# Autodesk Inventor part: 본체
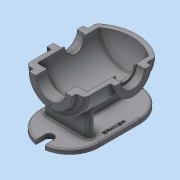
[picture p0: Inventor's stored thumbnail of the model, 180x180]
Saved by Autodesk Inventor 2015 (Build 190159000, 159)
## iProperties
Created: 2016-02
Part Number: 본체
Material: 알루미늄 6061
Document SubType Name: Modeling
Designer: mduedu
Density: 2.71 g/cm^3
Mass: 2164.68 g
Surface Area: 1516.74 cm^2
Volume: 798.775 cm^3
Appearance: 기본값
Author: mduedu
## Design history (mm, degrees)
sketch "스케치2"
  geometry: L1 (0, 90)-(0, -90); L2 (65, -65.993)-(65, 90); L3 (65, 90)-(0, 90); A1 r 100 centre (0, 10) between (0, -90) and (65, -65.993); 2 further points
  constraints: 6 end point, 2 point on circle, 1 centre point, 1 coincident, 1 horizontal, 1 midpoint, 1 parallel, 1 point on line, 1 vertical
  dimensions: "d3" = 180 distance of L1.start L1.end; "d5" = 130 diameter of L2 L1; "d6" = 100 radius of A1
revolve "회전1" sketch "스케치2" stored, may be unused: angle "d7" = 90 deg
sketch "스케치3"
  geometry: C1 r 47.5 at (0, 0); 1 further point
  constraints: 1 centre point, 1 coincident
  dimensions: "d8" = 95 diameter of C1
extrude "돌출2" join sketch "스케치3" distance "d10" = 10; taper "d11" = 0 deg
sketch "스케치5"
  geometry: L1 (47.5, 100)-(47.5, 90) reference; L2 (47.5, 90)-(65, 90) reference; L3 (65, 90)-(65, -65.993) reference; L4 (-65, -65.993)-(-65, 90) reference; L5 (-65, 90)-(-47.5, 90) reference; L6 (-47.5, 90)-(-47.5, 100) reference; L7 (-47.5, 100)-(47.5, 100) reference; L8 (55, 75)-(55, -61.239); L9 (0, 75)-(55, 75); L10 (0, 75)-(0, -80); A1 r 100 centre (0, 10) between (-65, -65.993) and (0, -90) reference; A2 r 100 centre (0, 10) between (0, -90) and (65, -65.993) reference; A3 r 90 centre (0, 10) between (0, -80) and (55, -61.239); 1 further point
  constraints: 6 end point, 2 point on circle, 1 centre point, 1 parallel, 1 perpendicular, 1 point on line, 1 vertical
  dimensions: "d13" = 10 distance between parallel lines of L3 L8; "d14" = 10 radial gap between concentric circles of A3 A1; "d15" = 15 distance between parallel lines of L9 L2
revolve "회전2" sketch "스케치5" stored, may be unused: angle "d16" = 90 deg
hole "구멍1" diameter "d19" = 65; stored, may be unused: countersink angle "d23" = 90 deg, drill point angle "d25" = 118 deg; dims "d17" = 10, "d18" = 10, "d20" = 6, "d21" = 4, "d22" = 2, "d24" = 8
node "작업 평면1"
sketch "스케치6"
  geometry: L1 (47.5, 100)-(-47.5, 100) reference; C1 r 40 at (0, -7); 1 further point
  constraints: 1 centre point, 1 vertical alignment
  dimensions: "d27" = 80 diameter of C1; "d29" = 107 distance from line of C1.centre L1
extrude "돌출3" join sketch "스케치6" stored distance "d30" = 10; taper "d31" = 0 deg
hole "구멍2" diameter "d34" = 42; stored, may be unused: countersink angle "d38" = 90 deg, drill point angle "d40" = 118 deg; dims "d32" = 10, "d33" = 10, "d35" = 6, "d36" = 52, "d37" = 18, "d39" = 8
sketch "스케치7" dims "d41" = 65
  geometry: C1 r 40 at (0, 0) reference; 3 further points
  constraints: 2 vertical alignment, 1 coincident, 2 other
hole "구멍3" sketch "스케치7" at (0, 32.5) diameter "d43" = 3.242; stored, may be unused: countersink angle "d47" = 90 deg, drill point angle "d49" = 118 deg; dims "d44" = 11, "d45" = 13, "d46" = 18, "d48" = 13
sketch "스케치8" dims "d53" = 80
  geometry: 3 further points
  constraints: 2 vertical alignment, 1 coincident, 2 other
hole "구멍4" sketch "스케치8" at (0, -40) diameter "d56" = 3.242; stored, may be unused: countersink angle "d60" = 90 deg, drill point angle "d62" = 118 deg; dims "d57" = 11, "d58" = 13, "d59" = 18, "d61" = 13
fillet "모깎기1" dims "d66" = 10
fillet "모깎기2" dims "d67" = 3
fillet "모깎기3" dims "d68" = 0.3
chamfer "모따기1" distance "d69" = 1; stored, may be unused: second distance "d70" = 2, angle "d71" = 45 deg
node "작업 평면5"
sketch "스케치10"
  geometry: L1 (-50, 66)-(50, 66); L2 (50, 66)-(50, 50); L3 (50, 50)-(-50, 50); L4 (-50, 50)-(-50, 66); 2 further points
  constraints: 8 end point, 2 horizontal, 2 vertical, 1 midpoint, 1 vertical alignment
  dimensions: "d177" = 50 distance from line of L3 point (0, 0); "d178" = 100 distance of L1.start L1.end; "d179" = 16 distance of L3.end L1.start
extrude "돌출5" join sketch "스케치10" stored distance "d84" = 10; taper "d85" = 0 deg
sketch "스케치21" dims "d180" = 220, "d182" = 130
  geometry: L1 (65, 58)-(-65, 58); L2 (-65, 58)-(-65, -32); L3 (-65, -32)-(65, -32); L4 (65, -32)-(65, 58); L5 (50, 50)-(50, 66) reference; 4 further points
  constraints: 8 end point, 3 horizontal alignment, 3 midpoint, 2 parallel, 1 horizontal, 1 perpendicular, 1 vertical alignment, 4 other
extrude "돌출13" join sketch "스케치21" distance "d183" = 10; taper "d184" = 0 deg
sketch "스케치11"
  geometry: L1 (-65, 80)-(-65, -61.239) reference; L2 (-100, -97)-(-100, -32) reference; L3 (-65, -42.793)-(-100, -63); L4 (-100, -97)-(-110, -97) reference; 1 further point
  constraints: 2 end point, 2 point on line
  dimensions: "d185" = 34 distance from line of L3.end L4; "d186" = 120 deg angle of L2 L3
feature "리브1" sketch "스케치11" dims "d88" = 1, "d89" = 16, "d90" = 0, "d91" = 0, "d92" = 1, "d93" = 1
fillet "모깎기12"
fillet "모깎기13"
fillet "모깎기16" dims "d167" = 3
fillet "모깎기18"
fillet "모깎기17" dims "d168" = 3
fillet "모깎기19" dims "d187" = 3
node "작업 평면6"
sketch "스케치19"
  geometry: L1 (75, -47)-(75, 33) reference; L2 (-75, -47)-(-75, 33) reference; L3 (75, -7)-(-75, -7); C1 r 22.5 at (0, -7); 1 further point
  constraints: 3 midpoint, 2 end point, 1 centre point
  dimensions: "d149" = 45 diameter of C1
extrude "돌출11" join sketch "스케치19" stored distance "d150" = 10; taper "d151" = 0 deg
hole "구멍6" diameter "d154" = 33.376; stored, may be unused: countersink angle "d158" = 90 deg, drill point angle "d160" = 118 deg; dims "d155" = 6, "d156" = 4, "d157" = 2, "d159" = 8, "d190" = 10, "d191" = 10
fillet "모깎기11" dims "d161" = 3
chamfer "모따기3" distance "d164" = 1; stored, may be unused: second distance "d165" = 2, angle "d166" = 45 deg
node "작업 평면9"
  node "작업 평면8"
sketch "스케치22" dims "d189" = 20
  geometry: L1 (-10, -123)-(10, -123); L2 (10, -123)-(10, -103); L3 (10, -103)-(-10, -103); L4 (-10, -103)-(-10, -123); A1 r 65 centre (0, -58) between (-65, -58) and (65, -58) reference; 2 further points
  constraints: 8 end point, 2 parallel, 1 horizontal, 1 horizontal alignment, 1 midpoint, 1 perpendicular, 1 tangent, 1 vertical alignment, 2 other
  dimensions: "d193" = 30 dimension on L1
extrude "돌출14" cut sketch "스케치22" stored distance "d194" = 10; taper "d195" = 0 deg
fillet "모깎기21" dims "d196" = 3
feature "분할1"
sketch "스케치23"
  geometry: L1 (-65, 32)-(-65, -58) reference; L2 (65, -58)-(65, 32) reference; L3 (-65, -13)-(65, -13); 2 further points
  constraints: 2 end point, 2 midpoint, 1 point on line, 1 other
  dimensions: "d197" = 12 distance from line of point (53, -13) L2
feature "엠보싱2" sketch "스케치23" dims "d8" = 95, "d198" = 0.5, "d199" = 0
node "솔리드2"
pattern_circular "원형 패턴1" dims angle "d51" = 360 deg
mirror "대칭1"
pattern_circular "원형 패턴2" dims angle "d64" = 360 deg
mirror "대칭3"
node "절단 모서리 투영1"
other parameters: "d26" = 75, "d136" = 175
